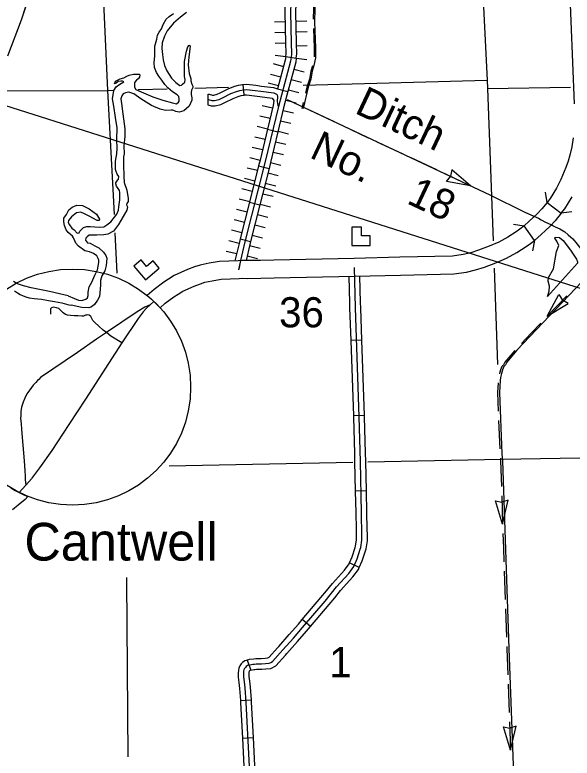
# Model space of a CAD drawing. Extents: x 1164457 to 1439835, y 1590918 to 1773502.
# Drawn here: x 1323402 to 1331207, y 1630737 to 1641151 of the extents above; entities that cross this region are included whole.
import ezdxf

# ---------------------------------------------------------------- set-up
doc = ezdxf.new("R2010")
doc.units = 0
for name, color, linetype in [('Level 15', 7, 'Continuous'), ('Level 24', 7, 'Continuous'), ('Level 29', 7, 'Continuous'), ('Level 32', 7, 'Continuous'), ('Level 35', 7, 'Continuous'), ('Level 37', 7, 'Continuous'), ('Level 4', 7, 'Continuous'), ('Level 43', 7, 'Continuous'), ('Level 45', 7, 'Continuous'), ('Level 46', 7, 'Continuous'), ('Level 5', 7, 'Continuous'), ('Level 58', 7, 'Continuous'), ('Level 63', 7, 'Continuous'), ('R_Draft', 7, 'Continuous')]:
    doc.layers.add(name, color=color, linetype=linetype)

msp = doc.modelspace()

# ---------------------------------------------------------------- linework, layer by layer
at = {"layer": 'Level 15'}
for points in [[(1331233, 1643547), (1331183, 1643438), (1331164, 1643382), (1331138, 1643272), (1331121, 1643176), (1331114, 1643097), (1331118, 1642885), (1331118, 1642805), (1331235, 1639903)], [(1331224, 1639430), (1331203, 1639302), (1331174, 1639184), (1331151, 1639103), (1331121, 1639011), (1331049, 1638845), (1330989, 1638722), (1330899, 1638577), (1330856, 1638520), (1331056, 1638370)], [(1330856, 1638520), (1330784, 1638432), (1330721, 1638366), (1330664, 1638311), (1330608, 1638260), (1330535, 1638195)], [(1331056, 1638370), (1331105, 1638435), (1331208, 1638600)], [(1331056, 1638370), (1330971, 1638265), (1330898, 1638189), (1330834, 1638128), (1330776, 1638075), (1330680, 1637991)], [(1330535, 1638195), (1330474, 1638150), (1330422, 1638111), (1330305, 1638034), (1330181, 1637965), (1330046, 1637909), (1329897, 1637854), (1329787, 1637818), (1329683, 1637793), (1329530, 1637772), (1328796, 1637755), (1328156, 1637738), (1327027, 1637716), (1326843, 1637711), (1326667, 1637709), (1326584, 1637710), (1326528, 1637704), (1326266, 1637696), (1326121, 1637672), (1325996, 1637646), (1325917, 1637620), (1325818, 1637581), (1325634, 1637499), (1325553, 1637447), (1325488, 1637405), (1325353, 1637305), (1325253, 1637218), (1325309, 1637172), (1325348, 1637135), (1325391, 1637092), (1325435, 1637045)], [(1325435, 1637045), (1325509, 1637110), (1325630, 1637199), (1325688, 1637237), (1325753, 1637278), (1325914, 1637350), (1326002, 1637384), (1326061, 1637404), (1326167, 1637426), (1326291, 1637447), (1326544, 1637455), (1326595, 1637460), (1326667, 1637459), (1326848, 1637461), (1327033, 1637466), (1328162, 1637488), (1328802, 1637505), (1329550, 1637522), (1329729, 1637547), (1329855, 1637577), (1329979, 1637618), (1330138, 1637676), (1330290, 1637740), (1330435, 1637820), (1330565, 1637906), (1330623, 1637949), (1330680, 1637991), (1330535, 1638195)], [(1325348, 1637135), (1325296, 1637090), (1325247, 1637043), (1325201, 1636991), (1325131, 1636898), (1324902, 1636555), (1324389, 1635764), (1324158, 1635412), (1323920, 1635047), (1323747, 1634802), (1323635, 1634655)], [(1323633, 1634652), (1323555, 1634560), (1323462, 1634458)], [(1323347, 1634522), (1323407, 1634487), (1323462, 1634458), (1323526, 1634427), (1323581, 1634404)], [(1323581, 1634404), (1323544, 1634362), (1323447, 1634279), (1323370, 1634218)]]:
    msp.add_lwpolyline(points, dxfattribs=at)
at = {"layer": 'Level 29'}
for p, q in [((1327040, 1641055), (1327190, 1641059)), ((1327340, 1641062), (1327490, 1641066)), ((1327044, 1640905), (1327194, 1640909)), ((1327344, 1640912), (1327494, 1640916)), ((1327047, 1640755), (1327197, 1640759)), ((1327348, 1640718), (1327498, 1640722)), ((1327047, 1640587), (1327196, 1640566)), ((1327344, 1640545), (1327493, 1640525)), ((1327021, 1640467), (1327166, 1640429)), ((1327310, 1640390), (1327455, 1640352)), ((1326982, 1640322), (1327127, 1640284)), ((1326949, 1640198), (1327094, 1640160)), ((1327272, 1640245), (1327417, 1640207)), ((1327233, 1640100), (1327378, 1640062)), ((1327233, 1640100), (1327378, 1640062)), ((1326866, 1639882), (1327012, 1639847)), ((1327195, 1639955), (1327340, 1639917)), ((1327158, 1639812), (1327304, 1639777)), ((1326831, 1639736), (1326977, 1639701)), ((1326831, 1639736), (1326977, 1639701)), ((1327123, 1639666), (1327269, 1639631)), ((1327123, 1639666), (1327269, 1639631)), ((1326796, 1639590), (1326942, 1639555)), ((1326761, 1639444), (1326907, 1639409)), ((1327088, 1639520), (1327234, 1639485)), ((1327053, 1639374), (1327198, 1639339)), ((1326726, 1639298), (1326872, 1639263)), ((1326726, 1639298), (1326872, 1639263)), ((1327018, 1639228), (1327163, 1639193)), ((1327018, 1639228), (1327163, 1639193)), ((1326691, 1639153), (1326837, 1639117)), ((1326983, 1639082), (1327128, 1639047)), ((1326655, 1639009), (1326800, 1638973)), ((1326946, 1638936), (1327091, 1638900)), ((1326618, 1638864), (1326764, 1638827)), ((1326618, 1638864), (1326764, 1638827)), ((1326582, 1638718), (1326727, 1638682)), ((1326909, 1638791), (1327055, 1638754)), ((1326909, 1638791), (1327055, 1638754)), ((1326873, 1638645), (1327018, 1638609)), ((1326545, 1638573), (1326691, 1638536)), ((1326836, 1638500), (1326981, 1638463)), ((1326508, 1638427), (1326654, 1638391)), ((1326508, 1638427), (1326654, 1638391)), ((1326799, 1638354), (1326945, 1638318)), ((1326799, 1638354), (1326945, 1638318)), ((1326472, 1638282), (1326617, 1638245)), ((1326763, 1638209), (1326908, 1638172)), ((1326435, 1638137), (1326581, 1638100)), ((1326398, 1637988), (1326544, 1637954)), ((1326398, 1637988), (1326544, 1637954)), ((1326726, 1638063), (1326872, 1638027)), ((1326690, 1637919), (1326836, 1637884)), ((1326690, 1637919), (1326836, 1637884)), ((1326363, 1637842), (1326509, 1637808)), ((1326655, 1637773), (1326801, 1637738))]:
    msp.add_line(p, q, dxfattribs=at)
for points in [[(1327288, 1644074), (1327317, 1643524), (1327309, 1643293), (1327317, 1643004), (1327328, 1642710), (1327336, 1642385), (1327337, 1642088), (1327333, 1641948), (1327323, 1641849), (1327314, 1641777), (1327302, 1641699), (1327279, 1641458), (1327270, 1641386), (1327265, 1641313), (1327262, 1641183), (1327272, 1640759), (1327275, 1640605), (1327270, 1640556)], [(1327270, 1640556), (1327262, 1640500), (1327094, 1639866), (1326909, 1639098), (1326620, 1637950), (1326563, 1637711), (1326536, 1637579)]]:
    msp.add_lwpolyline(points, dxfattribs=at)
at = {"layer": 'Level 32'}
for p, q in [((1327196, 1640566), (1327344, 1640545)), ((1326613, 1640028), (1326598, 1640177)), ((1327082, 1640116), (1327227, 1640077)), ((1326109, 1639889), (1326107, 1640039)), ((1326940, 1639549), (1327086, 1639514)), ((1326816, 1639037), (1326962, 1639000)), ((1326688, 1638525), (1326833, 1638488)), ((1326559, 1638013), (1326704, 1637976)), ((1326654, 1632111), (1326706, 1631970)), ((1326561, 1631543), (1326711, 1631554)), ((1326589, 1631017), (1326739, 1631025))]:
    msp.add_line(p, q, dxfattribs=at)
for points in [[(1327270, 1640556), (1327262, 1640500), (1327094, 1639866), (1326909, 1639098), (1326620, 1637950), (1326563, 1637711), (1326539, 1637586)], [(1327196, 1640566), (1327189, 1640515), (1327082, 1640116)], [(1327344, 1640545), (1327336, 1640486), (1327213, 1640025)], [(1326107, 1640039), (1326121, 1640039), (1326172, 1640026), (1326190, 1640026), (1326236, 1640038), (1326277, 1640057), (1326398, 1640118), (1326481, 1640150), (1326536, 1640166), (1326591, 1640176), (1326598, 1640177)], [(1326598, 1640177), (1326646, 1640182), (1326776, 1640166), (1326856, 1640154), (1327025, 1640132), (1327082, 1640116)], [(1326108, 1639964), (1326112, 1639964), (1326162, 1639952), (1326198, 1639951), (1326262, 1639967), (1326310, 1639990), (1326429, 1640049), (1326505, 1640079), (1326554, 1640093), (1326602, 1640102), (1326646, 1640106), (1326766, 1640092), (1326846, 1640080), (1327028, 1640056), (1327068, 1640041), (1327078, 1640029), (1327081, 1640006), (1327078, 1639938), (1327086, 1639880), (1327094, 1639866)], [(1326104, 1639889), (1326152, 1639877), (1326207, 1639875), (1326287, 1639896), (1326343, 1639922), (1326459, 1639981), (1326529, 1640007), (1326571, 1640019), (1326613, 1640027), (1326613, 1640028)], [(1326613, 1640028), (1326645, 1640031), (1326756, 1640018), (1326835, 1640006), (1327005, 1639983)], [(1327005, 1639983), (1327031, 1639953), (1327021, 1639883)], [(1327213, 1640025), (1327166, 1639847), (1327086, 1639514)], [(1327021, 1639883), (1326940, 1639549)], [(1326940, 1639549), (1326836, 1639116), (1326816, 1639037)], [(1327086, 1639514), (1326982, 1639080), (1326962, 1639000)], [(1326816, 1639037), (1326688, 1638525)], [(1326962, 1639000), (1326833, 1638488)], [(1326688, 1638525), (1326559, 1638013)], [(1326833, 1638488), (1326704, 1637976)], [(1326559, 1638013), (1326548, 1637968), (1326484, 1637703)], [(1326704, 1637976), (1326693, 1637933), (1326640, 1637709)], [(1325296, 1637090), (1325221, 1637053), (1325113, 1636990), (1324683, 1636700), (1324544, 1636605), (1324280, 1636419), (1323763, 1636068)], [(1324683, 1636700), (1324637, 1636735), (1324577, 1636787), (1324520, 1636839), (1324492, 1636869), (1324475, 1636906), (1324465, 1636923), (1324441, 1636943), (1324420, 1636946), (1324407, 1636945), (1324389, 1636943), (1324364, 1636930), (1324339, 1636928), (1324283, 1636932), (1324239, 1636936), (1324182, 1636938), (1324140, 1636942), (1324113, 1636952), (1324080, 1636974), (1324054, 1636999), (1324019, 1637036), (1323985, 1637048), (1323940, 1637054), (1323916, 1637046), (1323903, 1637032), (1323900, 1637004), (1323899, 1636958)], [(1324902, 1636555), (1324745, 1636649), (1324683, 1636700)], [(1323763, 1636068), (1323737, 1636044), (1323719, 1636027), (1323695, 1636002), (1323658, 1635961), (1323610, 1635899), (1323571, 1635839), (1323541, 1635778), (1323518, 1635725), (1323496, 1635654), (1323487, 1635593), (1323483, 1635536), (1323482, 1635495), (1323488, 1635425), (1323493, 1635339), (1323532, 1634902), (1323541, 1634763), (1323544, 1634686), (1323546, 1634640), (1323549, 1634597), (1323555, 1634560)], [(1326654, 1632111), (1326624, 1632100), (1326592, 1632077), (1326573, 1632056), (1326552, 1632029), (1326540, 1631998), (1326532, 1631969), (1326528, 1631929), (1326530, 1631870), (1326538, 1631796), (1326548, 1631714), (1326561, 1631543)], [(1326680, 1632040), (1326659, 1632033), (1326642, 1632021), (1326631, 1632008), (1326618, 1631991), (1326611, 1631974), (1326606, 1631955), (1326603, 1631927), (1326605, 1631875), (1326612, 1631805), (1326623, 1631721), (1326639, 1631515), (1326689, 1630530), (1326705, 1630176), (1326713, 1629923), (1326721, 1629528), (1326728, 1629342)], [(1326706, 1631970), (1326694, 1631965), (1326692, 1631964), (1326689, 1631961), (1326684, 1631954), (1326682, 1631949), (1326680, 1631941), (1326678, 1631925), (1326680, 1631880), (1326687, 1631814), (1326698, 1631729), (1326711, 1631554)], [(1326561, 1631543), (1326564, 1631511), (1326589, 1631017)], [(1326711, 1631554), (1326713, 1631520), (1326739, 1631025)], [(1326589, 1631017), (1326614, 1630526), (1326615, 1630490)], [(1326739, 1631025), (1326763, 1630534), (1326765, 1630497)]]:
    msp.add_lwpolyline(points, dxfattribs=at)
at = {"layer": 'Level 35'}
for points in [[(1325806, 1641185), (1325720, 1641117), (1325622, 1641036), (1325536, 1640926), (1325497, 1640850), (1325464, 1640758), (1325459, 1640678), (1325468, 1640597), (1325481, 1640522), (1325499, 1640443), (1325532, 1640367), (1325597, 1640264), (1325657, 1640202), (1325714, 1640163), (1325738, 1640167), (1325751, 1640178), (1325784, 1640207), (1325788, 1640244), (1325779, 1640288), (1325777, 1640375), (1325779, 1640498), (1325806, 1640643), (1325823, 1640704), (1325845, 1640726), (1325856, 1640717), (1325854, 1640669), (1325838, 1640562), (1325830, 1640452), (1325845, 1640327), (1325867, 1640257), (1325865, 1640226), (1325882, 1640180), (1325895, 1640152), (1325895, 1640132), (1325878, 1640095), (1325869, 1640064), (1325871, 1640036), (1325882, 1639988), (1325882, 1639957), (1325841, 1639871), (1325768, 1639808), (1325705, 1639786), (1325657, 1639795), (1325615, 1639814), (1325589, 1639814), (1325512, 1639812), (1325438, 1639830), (1325316, 1639880), (1325164, 1639974), (1325068, 1640044), (1324998, 1640069), (1324952, 1640060), (1324919, 1640042), (1324902, 1640014), (1324886, 1639974), (1324895, 1639911), (1324913, 1639763), (1324941, 1639555), (1324941, 1639445), (1324928, 1639316), (1324934, 1639204), (1324923, 1639162), (1324923, 1639119), (1324923, 1639051), (1324928, 1638893), (1324932, 1638803), (1324969, 1638695), (1324987, 1638579), (1324987, 1638537), (1324969, 1638506), (1324967, 1638487), (1324978, 1638460), (1324969, 1638414), (1324921, 1638327), (1324853, 1638213), (1324785, 1638121), (1324702, 1638079), (1324650, 1638068), (1324549, 1638062), (1324484, 1638064), (1324444, 1638062), (1324416, 1638042), (1324396, 1638024), (1324389, 1637996)], [(1324926, 1640267), (1324970, 1640291), (1325003, 1640304), (1325064, 1640320), (1325095, 1640322), (1325132, 1640322), (1325145, 1640320), (1325154, 1640309), (1325149, 1640278), (1325130, 1640254), (1325106, 1640236), (1325079, 1640201), (1325079, 1640166), (1325079, 1640138), (1325097, 1640107), (1325169, 1640074), (1325333, 1640004), (1325476, 1639956), (1325609, 1639916), (1325664, 1639905), (1325693, 1639927), (1325701, 1639942), (1325704, 1639975), (1325697, 1640006), (1325673, 1640030), (1325612, 1640074), (1325544, 1640128), (1325502, 1640174), (1325458, 1640236), (1325419, 1640290), (1325386, 1640341), (1325358, 1640411), (1325355, 1640477), (1325362, 1640578), (1325362, 1640627), (1325362, 1640710), (1325388, 1640809), (1325399, 1640866), (1325425, 1640907), (1325456, 1640956), (1325480, 1641017), (1325520, 1641089), (1325561, 1641129), (1325623, 1641172)], [(1324148, 1637214), (1324238, 1637177), (1324292, 1637155), (1324338, 1637147), (1324398, 1637166), (1324418, 1637188), (1324429, 1637219), (1324429, 1637265), (1324442, 1637342), (1324479, 1637407), (1324523, 1637504), (1324560, 1637580), (1324576, 1637681), (1324576, 1637712), (1324569, 1637736), (1324552, 1637775), (1324503, 1637808), (1324449, 1637830), (1324383, 1637846), (1324295, 1637909), (1324258, 1637951), (1324240, 1637984), (1324221, 1638025), (1324208, 1638049), (1324146, 1638102), (1324122, 1638141), (1324096, 1638198), (1324087, 1638253), (1324089, 1638304), (1324124, 1638352), (1324142, 1638389), (1324157, 1638420), (1324203, 1638455), (1324269, 1638483), (1324348, 1638481), (1324444, 1638433), (1324545, 1638358), (1324589, 1638288), (1324584, 1638268), (1324554, 1638268), (1324442, 1638328), (1324376, 1638365), (1324326, 1638385), (1324265, 1638376), (1324194, 1638323), (1324153, 1638271), (1324146, 1638240), (1324168, 1638207), (1324199, 1638163), (1324234, 1638139), (1324276, 1638093), (1324302, 1638098), (1324313, 1638119), (1324339, 1638150), (1324365, 1638172), (1324409, 1638187), (1324455, 1638187), (1324523, 1638179), (1324589, 1638174), (1324646, 1638183), (1324690, 1638207), (1324744, 1638249), (1324795, 1638314), (1324830, 1638360), (1324852, 1638413), (1324858, 1638459), (1324874, 1638557), (1324871, 1638617), (1324871, 1638660), (1324865, 1638689), (1324847, 1638717), (1324825, 1638750), (1324814, 1638781), (1324817, 1638798), (1324845, 1638840), (1324852, 1638847), (1324856, 1638886), (1324834, 1638917), (1324821, 1638954), (1324812, 1638985), (1324812, 1639033), (1324812, 1639101), (1324830, 1639204), (1324836, 1639283), (1324830, 1639406), (1324836, 1639568), (1324812, 1639715), (1324786, 1639870), (1324768, 1639976), (1324788, 1640092), (1324821, 1640142), (1324871, 1640179), (1324930, 1640212), (1324909, 1640221), (1324887, 1640221), (1324849, 1640219), (1324819, 1640192), (1324797, 1640184), (1324812, 1640221), (1324876, 1640256), (1324926, 1640267)], [(1324389, 1637996), (1324418, 1637956), (1324455, 1637952), (1324523, 1637913), (1324576, 1637886), (1324644, 1637825), (1324674, 1637779), (1324692, 1637742), (1324685, 1637689), (1324679, 1637637), (1324663, 1637565), (1324622, 1637495), (1324602, 1637431), (1324602, 1637363), (1324593, 1637256), (1324589, 1637203), (1324559, 1637154), (1324517, 1637093), (1324488, 1637069), (1324467, 1637054), (1324438, 1637048), (1324339, 1637052), (1324192, 1637081)], [(1331083, 1637989), (1331183, 1637853), (1331267, 1637729), (1331285, 1637692), (1331285, 1637679), (1331285, 1637673), (1330863, 1637203), (1330888, 1637281), (1330890, 1637349), (1330874, 1637419), (1330872, 1637424)], [(1330874, 1637419), (1330878, 1637470), (1330948, 1637593), (1330987, 1637837), (1331019, 1637920), (1330991, 1637980), (1330967, 1638024), (1330971, 1638036), (1331029, 1638031), (1331083, 1637989)], [(1324148, 1637214), (1324027, 1637242), (1323886, 1637273), (1323768, 1637298), (1323629, 1637327), (1323521, 1637352), (1323437, 1637381), (1323383, 1637417)], [(1323397, 1637286), (1323440, 1637257)], [(1323440, 1637257), (1323478, 1637234), (1323518, 1637216), (1323557, 1637202), (1323602, 1637188), (1323670, 1637178), (1323774, 1637166), (1323874, 1637151), (1323957, 1637136), (1324059, 1637115), (1324158, 1637090), (1324192, 1637081)]]:
    msp.add_lwpolyline(points, dxfattribs=at)
at = {"layer": 'Level 37'}
for points in [[(1330856, 1638520), (1330834, 1638668)], [(1331205, 1638391), (1331056, 1638370)], [(1330387, 1638220), (1330535, 1638195)], [(1330679, 1637991), (1330654, 1637843)]]:
    msp.add_lwpolyline(points, dxfattribs=at)
at = {"layer": 'Level 4'}
for points in [[(1329688, 1647758), (1329756, 1645487), (1329762, 1645365), (1330018, 1640234), (1330022, 1640121), (1330101, 1637987)], [(1330115, 1637604), (1330164, 1636253)], [(1330212, 1634927), (1335440, 1635016), (1340328, 1635089)], [(1325564, 1634833), (1328137, 1634885)], [(1328348, 1634889), (1330212, 1634927)]]:
    msp.add_lwpolyline(points, dxfattribs=at)
at = {"layer": 'Level 43'}
for p, q in [((1329522, 1638979), (1329506, 1638889)), ((1329784, 1638757), (1329522, 1638979)), ((1329446, 1638818), (1329505, 1638888)), ((1329784, 1638757), (1329446, 1638818)), ((1330859, 1636929), (1331023, 1637231)), ((1331023, 1637231), (1331071, 1637153)), ((1331152, 1637108), (1331072, 1637152)), ((1330859, 1636929), (1331152, 1637108)), ((1330234, 1634015), (1330134, 1634343)), ((1330134, 1634343), (1330223, 1634323)), ((1330312, 1634349), (1330225, 1634323)), ((1330234, 1634015), (1330312, 1634349)), ((1330345, 1630849), (1330244, 1631177)), ((1330244, 1631177), (1330334, 1631157)), ((1330422, 1631183), (1330335, 1631157)), ((1330345, 1630849), (1330422, 1631183))]:
    msp.add_line(p, q, dxfattribs=at)
for points in [[(1327647, 1644449), (1327666, 1643963), (1327670, 1643268), (1327676, 1642789), (1327699, 1642297), (1327701, 1642119), (1327696, 1642007), (1327694, 1641933), (1327641, 1641725), (1327605, 1641319), (1327602, 1641236), (1327599, 1641055), (1327614, 1640687), (1327612, 1640626), (1327614, 1640549), (1327590, 1640442), (1327567, 1640360), (1327549, 1640251), (1327511, 1640136), (1327439, 1639840)], [(1323511, 1644058), (1323875, 1643603), (1323955, 1643507), (1324001, 1643446), (1324055, 1643360), (1324095, 1643283), (1324126, 1643163), (1324133, 1643094), (1324096, 1642973), (1324104, 1642956), (1324109, 1642921), (1324079, 1642848), (1324026, 1642680), (1323969, 1642506), (1323489, 1641076)], [(1323557, 1641279), (1323489, 1641076), (1323425, 1640905)], [(1327586, 1641290), (1327584, 1641236), (1327581, 1641092)], [(1323489, 1641076), (1323300, 1640574)], [(1327585, 1640960), (1327595, 1640687), (1327593, 1640626), (1327595, 1640564)], [(1327570, 1640435), (1327549, 1640360), (1327530, 1640251), (1327493, 1640136), (1327472, 1640052)], [(1327215, 1639963), (1330053, 1638631), (1330547, 1638385), (1330736, 1638300), (1330776, 1638278), (1330834, 1638247), (1330908, 1638212), (1330969, 1638179), (1331036, 1638151), (1331106, 1638109), (1331153, 1638070), (1331215, 1638011), (1331279, 1637940), (1331342, 1637854), (1331501, 1637605)], [(1327215, 1639963), (1327394, 1639879)], [(1327441, 1639924), (1327420, 1639840)], [(1327514, 1639823), (1327872, 1639655)], [(1327992, 1639599), (1328350, 1639430)], [(1328470, 1639374), (1328828, 1639206)], [(1328948, 1639150), (1329306, 1638982)], [(1329426, 1638926), (1329784, 1638757)], [(1329904, 1638701), (1330053, 1638631), (1330083, 1638616)], [(1330083, 1638616), (1330260, 1638528)], [(1330378, 1638469), (1330547, 1638385), (1330680, 1638325)], [(1330916, 1638208), (1330969, 1638179), (1331036, 1638151), (1331106, 1638109), (1331153, 1638070), (1331189, 1638036)], [(1331528, 1637605), (1330434, 1636452), (1330294, 1636286), (1330272, 1636249), (1330252, 1636222), (1330232, 1636178), (1330218, 1636126), (1330206, 1636072), (1330199, 1636026), (1330189, 1635859), (1330225, 1635001), (1330231, 1634903), (1330320, 1632272), (1330417, 1629632), (1330424, 1629223), (1330503, 1626944), (1330539, 1625302), (1330574, 1624205), (1330581, 1623987)], [(1331132, 1637216), (1330859, 1636929)], [(1330769, 1636833), (1330632, 1636689)], [(1330632, 1636689), (1330496, 1636546)], [(1330405, 1636450), (1330267, 1636286), (1330245, 1636249), (1330225, 1636222), (1330205, 1636178), (1330190, 1636126), (1330190, 1636123)], [(1330170, 1635993), (1330161, 1635859), (1330173, 1635598)], [(1330178, 1635466), (1330195, 1635070)], [(1330202, 1634938), (1330204, 1634903), (1330217, 1634543)], [(1330221, 1634411), (1330234, 1634015)], [(1330239, 1633883), (1330246, 1633685)], [(1330246, 1633685), (1330252, 1633487)], [(1330257, 1633355), (1330270, 1632960)], [(1330274, 1632828), (1330288, 1632432)], [(1330292, 1632300), (1330293, 1632272), (1330307, 1631904)], [(1330312, 1631772), (1330326, 1631377)], [(1330331, 1631245), (1330345, 1630849)]]:
    msp.add_lwpolyline(points, dxfattribs=at)
at = {"layer": 'Level 45'}
for p, q in [((1328262, 1636593), (1328112, 1636587)), ((1328298, 1635537), (1328148, 1635532)), ((1328325, 1634481), (1328175, 1634477)), ((1328226, 1633410), (1328090, 1633471)), ((1327542, 1632581), (1327427, 1632678))]:
    msp.add_line(p, q, dxfattribs=at)
for points in [[(1326680, 1632040), (1326734, 1632053), (1326756, 1632055), (1326783, 1632058), (1326857, 1632060), (1326914, 1632063), (1326964, 1632066), (1326987, 1632078), (1327011, 1632091), (1327156, 1632252), (1327303, 1632420), (1327431, 1632565), (1327746, 1632938), (1327909, 1633135), (1328079, 1633323), (1328149, 1633420), (1328198, 1633529), (1328240, 1633665), (1328248, 1633689), (1328264, 1633789), (1328264, 1633854), (1328257, 1634174), (1328241, 1634895), (1328224, 1635518), (1328171, 1637046), (1328159, 1637613)], [(1328094, 1637116), (1328086, 1637487)], [(1328244, 1637119), (1328236, 1637490)], [(1328112, 1636587), (1328096, 1637044), (1328094, 1637116)], [(1328262, 1636593), (1328246, 1637048), (1328244, 1637119)], [(1328130, 1636060), (1328112, 1636587)], [(1328280, 1636065), (1328262, 1636593)], [(1328148, 1635532), (1328130, 1636060)], [(1328298, 1635537), (1328280, 1636065)], [(1328163, 1635005), (1328149, 1635516), (1328148, 1635532)], [(1328313, 1635009), (1328299, 1635520), (1328298, 1635537)], [(1328175, 1634477), (1328166, 1634893), (1328163, 1635005)], [(1328325, 1634481), (1328316, 1634897), (1328313, 1635009)], [(1328187, 1633949), (1328182, 1634172), (1328175, 1634477)], [(1328337, 1633953), (1328332, 1634176), (1328325, 1634481)], [(1328090, 1633471), (1328128, 1633556), (1328169, 1633687), (1328175, 1633706), (1328189, 1633795), (1328189, 1633853), (1328187, 1633949)], [(1328226, 1633410), (1328268, 1633502), (1328312, 1633642), (1328321, 1633671), (1328339, 1633783), (1328339, 1633854), (1328337, 1633953)], [(1327767, 1633081), (1327852, 1633184), (1328020, 1633370), (1328083, 1633458), (1328090, 1633471)], [(1327882, 1632985), (1327965, 1633086), (1328137, 1633276), (1328214, 1633382), (1328226, 1633410)], [(1327427, 1632678), (1327688, 1632986), (1327767, 1633081)], [(1327542, 1632581), (1327803, 1632890), (1327882, 1632985)], [(1327081, 1632281), (1327100, 1632302), (1327246, 1632470), (1327374, 1632614), (1327427, 1632678)], [(1327193, 1632181), (1327212, 1632202), (1327359, 1632371), (1327487, 1632516), (1327542, 1632581)], [(1326654, 1632111), (1326689, 1632123), (1326748, 1632130), (1326778, 1632133), (1326854, 1632135), (1326910, 1632138), (1326943, 1632140), (1326964, 1632151), (1327081, 1632281)], [(1326706, 1631970), (1326747, 1631979), (1326764, 1631980), (1326788, 1631983), (1326860, 1631985), (1326918, 1631988), (1326985, 1631992), (1327058, 1632031), (1327193, 1632181)]]:
    msp.add_lwpolyline(points, dxfattribs=at)
at = {"layer": 'Level 46'}
for points in [[(1327195, 1640563), (1327200, 1640608), (1327197, 1640757), (1327187, 1641183), (1327190, 1641317), (1327195, 1641393), (1327204, 1641466), (1327227, 1641709), (1327240, 1641788), (1327249, 1641857), (1327258, 1641953), (1327262, 1642089), (1327261, 1642384), (1327253, 1642708), (1327242, 1643002), (1327234, 1643293), (1327242, 1643523), (1327213, 1644070)], [(1327344, 1640548), (1327350, 1640601), (1327347, 1640760), (1327337, 1641183), (1327340, 1641310), (1327344, 1641379), (1327354, 1641450), (1327376, 1641690), (1327389, 1641767), (1327398, 1641840), (1327408, 1641943), (1327412, 1642088), (1327411, 1642386), (1327403, 1642712), (1327392, 1643007), (1327384, 1643292), (1327392, 1643524), (1327363, 1644078)]]:
    msp.add_lwpolyline(points, dxfattribs=at)
at = {"layer": 'Level 5'}
for points in [[(1324508, 1644314), (1324700, 1640092)], [(1327439, 1640165), (1330018, 1640234)], [(1319390, 1640085), (1324700, 1640092)], [(1324700, 1640092), (1324784, 1640094)], [(1324700, 1640092), (1324778, 1638622), (1324791, 1638354)], [(1325127, 1640103), (1325534, 1640114)], [(1325922, 1640124), (1326396, 1640137)], [(1330022, 1640121), (1331184, 1640140)], [(1324804, 1638095), (1324832, 1637533)], [(1324965, 1633269), (1324966, 1633226), (1324982, 1630757)]]:
    msp.add_lwpolyline(points, dxfattribs=at)
at = {"layer": 'Level 58'}
for points in [[(1328123, 1637921), (1328377, 1637921), (1328377, 1638055), (1328256, 1638055), (1328256, 1638175), (1328123, 1638175)], [(1325231, 1637436), (1325425, 1637600), (1325339, 1637703), (1325247, 1637625), (1325170, 1637717), (1325067, 1637630)]]:
    msp.add_lwpolyline(points, close=True, dxfattribs=at)
at = {"layer": 'Level 63'}
msp.add_circle((1324209, 1635935), 1655, dxfattribs=at)
at = {"layer": 'R_Draft'}
msp.add_line((1375114, 1623387), (1297809, 1647974), dxfattribs=at)

# ---------------------------------------------------------------- texts
at = {"layer": 'Level 24'}
msp.add_text('Cantwell', height=528, dxfattribs=at).set_placement((1323535, 1633505))
at = {"layer": 'Level 43'}
for s, p in [('Ditch', (1328145, 1639782)), ('No.    18', (1327513, 1639159))]:
    msp.add_text(s, height=422, rotation=334.7591, dxfattribs=at).set_placement(p)
at = {"layer": 'Level 5'}
for s, p in [('36', (1327103, 1636773)), ('1', (1327804, 1631871))]:
    msp.add_text(s, height=422, dxfattribs=at).set_placement(p)

doc.saveas('drawing.dxf')
